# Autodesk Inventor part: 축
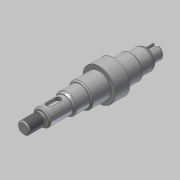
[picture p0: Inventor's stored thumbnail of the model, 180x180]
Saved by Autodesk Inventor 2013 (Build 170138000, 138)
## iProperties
Created: 2019-09
Part Number: 축
Material: 강철, 연강
Document SubType Name: Modeling
Designer: mduedu
Density: 7.86 g/cm^3
Mass: 210.278 g
Surface Area: 69.4769 cm^2
Volume: 26.7529 cm^3
Author: mduedu
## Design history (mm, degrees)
sketch "스케치1"
  geometry: L1 (0, 0)-(15, 0); L2 (15, 0)-(15, 5); L3 (15, 5)-(0, 5); L4 (0, 5)-(0, 0); L5 (15, 0)-(34, 0); L6 (34, 0)-(34, 7); L7 (34, 7)-(15, 7); L8 (15, 7)-(15, 0); L9 (34, 0)-(47, 0); L10 (47, 0)-(47, 8.5); L11 (47, 8.5)-(34, 8.5); L12 (34, 8.5)-(34, 0); L13 (47, 0)-(63, 0); L14 (63, 0)-(63, 10); L15 (63, 10)-(47, 10); L16 (47, 10)-(47, 0); L17 (63, 0)-(75, 0); L18 (75, 0)-(75, 13.5); L19 (75, 13.5)-(63, 13.5); L20 (63, 13.5)-(63, 0); L21 (75, 0)-(90, 0); L22 (90, 0)-(90, 10); L23 (90, 10)-(75, 10); L24 (75, 10)-(75, 0); L25 (90, 0)-(102, 0); L26 (102, 0)-(102, 8.5); L27 (102, 8.5)-(90, 8.5); L28 (90, 8.5)-(90, 0); L29 (102, 0)-(111, 0); L30 (111, 0)-(111, 5.5); L31 (111, 5.5)-(102, 5.5); L32 (102, 5.5)-(102, 0)
  constraints: 64 end point, 16 parallel, 8 horizontal, 8 perpendicular
  dimensions: "d0" = 111 distance between parallel lines of L30 L4; "d2" = 15 distance of L2.end L3.end; "d3" = 19 distance of L6.end L7.end; "d4" = 12 distance of L18.end L19.end; "d5" = 15 distance of L22.end L23.end; "d6" = 12 distance of L26.end L27.end; "d7" = 9 distance of L30.end L31.end; "d8" = 16 distance of L14.end L15.end; "d9" = 10 diameter of L3 L1; "d10" = 14 diameter of L7 L5; "d11" = 17 diameter of L11 L9; "d12" = 20 diameter of L15 L13; "d13" = 27 diameter of L19 L17; "d14" = 20 diameter of L23 L21; "d15" = 17 diameter of L27 L25; "d16" = 11 diameter of L31 L29
revolve "회전1" sketch "스케치1" stored, may be unused: angle "d17" = 90 deg
sketch "스케치2"
  geometry: L1 (0, -5)-(0, 5) reference; L2 (0, 5)-(15, 5) reference; L3 (15, 5)-(15, 7) reference; L4 (15, 7)-(34, 7) reference; L5 (34, 7)-(34, 8.5) reference; L6 (34, 8.5)-(47, 8.5) reference; L7 (47, 8.5)-(47, 10) reference; L8 (47, 10)-(63, 10) reference; L9 (63, 10)-(63, 13.5) reference; L10 (63, 13.5)-(75, 13.5) reference; L11 (75, 13.5)-(75, 10) reference; L12 (75, 10)-(90, 10) reference; L13 (90, 10)-(90, 8.5) reference; L14 (90, 8.5)-(102, 8.5) reference; L15 (102, 8.5)-(102, 5.5) reference; L16 (102, 5.5)-(111, 5.5) reference; L17 (111, 5.5)-(111, -5.5) reference; L18 (111, -5.5)-(102, -5.5) reference; L19 (102, -5.5)-(102, -8.5) reference; L20 (102, -8.5)-(90, -8.5) reference; L21 (90, -8.5)-(90, -10) reference; L22 (90, -10)-(75, -10) reference; L23 (75, -10)-(75, -13.5) reference; L24 (75, -13.5)-(63, -13.5) reference; L25 (63, -13.5)-(63, -10) reference; L26 (63, -10)-(47, -10) reference; L27 (47, -10)-(47, -8.5) reference; L28 (47, -8.5)-(34, -8.5) reference; L29 (34, -8.5)-(34, -7) reference; L30 (34, -7)-(15, -7) reference; L31 (15, -7)-(15, -5) reference; L32 (15, -5)-(0, -5) reference; L33 (0, 0)-(111, 0); L34 (15, 5)-(12.014, 5); L35 (13.4, 4.2)-(15, 4.2); L36 (15, 4.2)-(15, 5); L37 (12.014, 5)-(13.4, 4.2)
  constraints: 10 end point, 1 horizontal, 1 midpoint, 1 parallel, 1 vertical
  dimensions: "d18" = 30 deg angle of L2 L37; "d19" = 8.4 diameter of L35 L33; "d21" = 2.986 distance from line of L34.end L36
revolve "회전2" sketch "스케치2" stored, may be unused: angle "d22" = 90 deg
fillet "모깎기1" dims "d23" = 0.6
feature "스레드1" dims "d24" = 10, "d25" = 0
chamfer "모따기1" distance "d26" = 1; stored, may be unused: second distance "d27" = 2, angle "d28" = 45 deg
chamfer "모따기2" distance "d29" = 1; stored, may be unused: second distance "d30" = 2, angle "d31" = 45 deg
chamfer "모따기3" distance "d32" = 1.819; stored, may be unused: second distance "d33" = 2, angle "d34" = 30 deg
fillet "모깎기2" dims "d35" = 2
chamfer "모따기4" distance "d36" = 1; stored, may be unused: second distance "d37" = 2, angle "d38" = 30 deg
fillet "모깎기3" dims "d39" = 0.3
chamfer "모따기5" distance "d40" = 1; stored, may be unused: second distance "d41" = 2, angle "d42" = 30 deg
chamfer "모따기6" distance "d43" = 1.819; stored, may be unused: second distance "d44" = 2, angle "d45" = 30 deg
chamfer "모따기7" distance "d46" = 0.5; stored, may be unused: second distance "d47" = 2, angle "d48" = 30 deg
fillet "모깎기4" dims "d49" = 2
node "작업 평면1"
sketch "스케치3" dims "d51" = 12
  geometry: L1 (3, -2.5)-(-4, -2.5); L2 (-4, -2.5)-(-4, 2.5); L3 (-4, 2.5)-(3, 2.5); L4 (3, 2.5)-(3, -2.5); L5 (-9.5, 7.45)-(-9.5, -7.45) reference; 3 further points
  constraints: 8 end point, 2 midpoint, 2 parallel, 2 vertical alignment, 1 horizontal, 1 horizontal alignment, 1 perpendicular, 4 other
  dimensions: "d50" = 3 dimension on L5; "d52" = 5 distance between parallel lines of L3 L1
extrude "돌출1" cut sketch "스케치3" distance "d53" = 3; taper "d54" = 0 deg
node "작업 평면3"
sketch "스케치4"
  geometry: L1 (-4.5, -5)-(-4.5, 5) reference; L2 (-4.5, -2)-(1.5, -2); L3 (1.5, -2)-(1.5, 2); L4 (1.5, 2)-(-4.5, 2); L5 (-4.5, 2)-(-4.5, -2); 3 further points
  constraints: 8 end point, 2 horizontal alignment, 2 midpoint, 2 parallel, 1 horizontal, 1 perpendicular, 1 point on line, 1 vertical alignment, 2 other
  dimensions: "d55" = 4 distance between parallel lines of L4 L2; "d57" = 8 dimension on L1
extrude "돌출2" cut sketch "스케치4" distance "d58" = 2.5; taper "d59" = 0 deg
sketch "스케치5"
  geometry: A1 r 5.5 centre (2, -3) between (0, 2.123) and (4, 2.123) reference; 2 further points
  constraints: 1 point on circle
hole "구멍1" sketch "스케치5" at (2, -8.5) diameter "d60" = 2.459; stored, may be unused: countersink angle "d64" = 90 deg, drill point angle "d66" = 118 deg; dims "d61" = 6, "d62" = 4, "d63" = 2, "d65" = 5
node "솔리드1"
node "절단 모서리 투영1"
